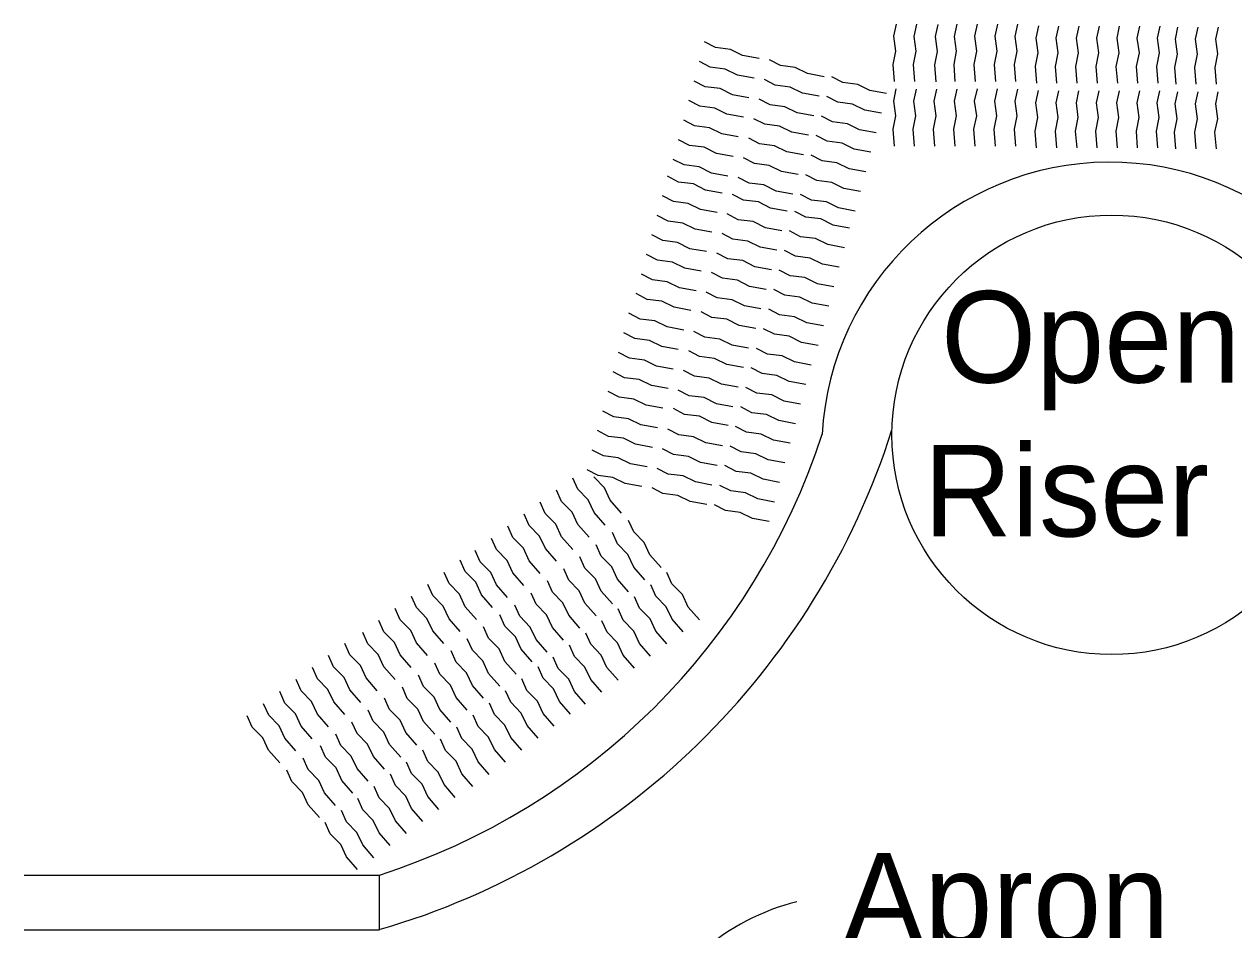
# Model space of a CAD drawing. Extents: x 539344 to 540004, y 1574686 to 1575110.
# Drawn here: x 539692.02 to 539725.07, y 1574776.96 to 1574801.69 of the extents above; entities that cross this region are included whole.
import ezdxf

# ---------------------------------------------------------------- set-up
doc = ezdxf.new("R2010")
doc.units = 0
doc.layers.add('Default', color=7, linetype='Continuous')

msp = doc.modelspace()

# ---------------------------------------------------------------- linework, layer by layer
at = {"layer": 'Default'}
for p, q in [((539692.024, 1574778.454), (539701.728, 1574778.454)), ((539701.728, 1574776.962), (539701.728, 1574778.454)), ((539692.024, 1574776.962), (539701.728, 1574776.962))]:
    msp.add_line(p, q, dxfattribs=at)
for points in [[(539715.804, 1574800.126), (539715.768, 1574800.586), (539715.84, 1574800.952), (539715.784, 1574801.36), (539715.858, 1574801.688)], [(539716.356, 1574800.126), (539716.32, 1574800.584), (539716.394, 1574800.952), (539716.338, 1574801.356), (539716.41, 1574801.688)], [(539716.938, 1574800.118), (539716.902, 1574800.576), (539716.978, 1574800.944), (539716.92, 1574801.348), (539716.994, 1574801.678)], [(539717.464, 1574800.126), (539717.428, 1574800.584), (539717.5, 1574800.952), (539717.444, 1574801.356), (539717.516, 1574801.688)], [(539718.018, 1574800.126), (539717.98, 1574800.586), (539718.054, 1574800.952), (539717.998, 1574801.36), (539718.07, 1574801.688)], [(539718.568, 1574800.128), (539718.53, 1574800.588), (539718.606, 1574800.956), (539718.55, 1574801.36), (539718.622, 1574801.688)], [(539719.12, 1574800.126), (539719.082, 1574800.584), (539719.158, 1574800.952), (539719.102, 1574801.356), (539719.174, 1574801.688)], [(539719.69, 1574800.078), (539719.654, 1574800.538), (539719.728, 1574800.906), (539719.67, 1574801.31), (539719.746, 1574801.64)], [(539720.24, 1574800.076), (539720.202, 1574800.536), (539720.278, 1574800.902), (539720.222, 1574801.31), (539720.294, 1574801.638)], [(539720.796, 1574800.076), (539720.756, 1574800.536), (539720.832, 1574800.902), (539720.776, 1574801.31), (539720.85, 1574801.638)], [(539721.35, 1574800.076), (539721.31, 1574800.536), (539721.386, 1574800.902), (539721.33, 1574801.31), (539721.402, 1574801.638)], [(539721.902, 1574800.076), (539721.862, 1574800.536), (539721.94, 1574800.902), (539721.882, 1574801.31), (539721.954, 1574801.638)], [(539722.452, 1574800.076), (539722.416, 1574800.534), (539722.492, 1574800.902), (539722.434, 1574801.308), (539722.508, 1574801.638)], [(539723.006, 1574800.076), (539722.968, 1574800.536), (539723.044, 1574800.902), (539722.988, 1574801.31), (539723.06, 1574801.638)], [(539723.496, 1574800.048), (539723.458, 1574800.508), (539723.532, 1574800.874), (539723.476, 1574801.28), (539723.548, 1574801.608)], [(539724.048, 1574800.048), (539724.012, 1574800.508), (539724.084, 1574800.874), (539724.03, 1574801.28), (539724.102, 1574801.608)], [(539724.602, 1574800.048), (539724.566, 1574800.508), (539724.638, 1574800.876), (539724.584, 1574801.28), (539724.656, 1574801.61)], [(539712.106, 1574800.748), (539711.652, 1574800.832), (539711.318, 1574800.998), (539710.912, 1574801.048), (539710.614, 1574801.204)], [(539711.964, 1574800.214), (539711.512, 1574800.298), (539711.178, 1574800.462), (539710.77, 1574800.514), (539710.472, 1574800.67)], [(539713.882, 1574800.254), (539713.428, 1574800.338), (539713.092, 1574800.504), (539712.686, 1574800.558), (539712.388, 1574800.712)], [(539713.74, 1574799.72), (539713.286, 1574799.804), (539712.95, 1574799.97), (539712.546, 1574800.022), (539712.248, 1574800.176)], [(539715.586, 1574799.792), (539715.132, 1574799.874), (539714.796, 1574800.042), (539714.392, 1574800.092), (539714.094, 1574800.248)], [(539711.822, 1574799.678), (539711.372, 1574799.76), (539711.036, 1574799.928), (539710.628, 1574799.978), (539710.328, 1574800.134)], [(539715.798, 1574798.36), (539715.762, 1574798.82), (539715.836, 1574799.186), (539715.78, 1574799.59), (539715.852, 1574799.922)], [(539716.348, 1574798.358), (539716.314, 1574798.818), (539716.386, 1574799.184), (539716.332, 1574799.588), (539716.404, 1574799.918)], [(539716.902, 1574798.358), (539716.866, 1574798.818), (539716.938, 1574799.184), (539716.886, 1574799.588), (539716.956, 1574799.918)], [(539717.456, 1574798.358), (539717.42, 1574798.818), (539717.494, 1574799.184), (539717.438, 1574799.588), (539717.512, 1574799.918)], [(539718.008, 1574798.36), (539717.974, 1574798.82), (539718.048, 1574799.186), (539717.992, 1574799.59), (539718.066, 1574799.922)], [(539718.562, 1574798.36), (539718.526, 1574798.822), (539718.598, 1574799.186), (539718.542, 1574799.59), (539718.616, 1574799.922)], [(539719.114, 1574798.358), (539719.078, 1574798.818), (539719.152, 1574799.184), (539719.096, 1574799.588), (539719.168, 1574799.918)], [(539719.684, 1574798.31), (539719.646, 1574798.77), (539719.72, 1574799.138), (539719.666, 1574799.544), (539719.738, 1574799.874)], [(539720.234, 1574798.31), (539720.198, 1574798.768), (539720.272, 1574799.138), (539720.216, 1574799.542), (539720.29, 1574799.872)], [(539720.79, 1574798.31), (539720.752, 1574798.768), (539720.824, 1574799.138), (539720.772, 1574799.542), (539720.842, 1574799.872)], [(539721.344, 1574798.31), (539721.306, 1574798.768), (539721.378, 1574799.138), (539721.324, 1574799.542), (539721.396, 1574799.872)], [(539721.896, 1574798.31), (539721.858, 1574798.768), (539721.932, 1574799.138), (539721.876, 1574799.542), (539721.95, 1574799.872)], [(539722.446, 1574798.31), (539722.41, 1574798.768), (539722.484, 1574799.136), (539722.428, 1574799.54), (539722.502, 1574799.872)], [(539723, 1574798.31), (539722.964, 1574798.768), (539723.038, 1574799.138), (539722.98, 1574799.542), (539723.056, 1574799.872)], [(539723.488, 1574798.282), (539723.452, 1574798.74), (539723.526, 1574799.106), (539723.47, 1574799.512), (539723.544, 1574799.842)], [(539724.042, 1574798.282), (539724.004, 1574798.74), (539724.08, 1574799.106), (539724.024, 1574799.512), (539724.098, 1574799.842)], [(539724.596, 1574798.282), (539724.558, 1574798.742), (539724.632, 1574799.106), (539724.578, 1574799.514), (539724.65, 1574799.842)], [(539711.678, 1574799.146), (539711.224, 1574799.23), (539710.89, 1574799.396), (539710.484, 1574799.448), (539710.186, 1574799.604)], [(539713.598, 1574799.186), (539713.144, 1574799.268), (539712.81, 1574799.434), (539712.404, 1574799.486), (539712.104, 1574799.64)], [(539715.444, 1574799.258), (539714.99, 1574799.34), (539714.658, 1574799.506), (539714.25, 1574799.558), (539713.952, 1574799.714)], [(539715.302, 1574798.722), (539714.85, 1574798.806), (539714.516, 1574798.97), (539714.11, 1574799.02), (539713.81, 1574799.178)], [(539711.534, 1574798.61), (539711.082, 1574798.696), (539710.75, 1574798.86), (539710.342, 1574798.914), (539710.042, 1574799.068)], [(539713.454, 1574798.654), (539713, 1574798.736), (539712.662, 1574798.902), (539712.258, 1574798.954), (539711.96, 1574799.108)], [(539711.394, 1574798.076), (539710.942, 1574798.16), (539710.606, 1574798.326), (539710.2, 1574798.378), (539709.9, 1574798.534)], [(539713.312, 1574798.118), (539712.858, 1574798.202), (539712.52, 1574798.368), (539712.116, 1574798.42), (539711.818, 1574798.574)], [(539715.158, 1574798.19), (539714.704, 1574798.272), (539714.37, 1574798.44), (539713.964, 1574798.49), (539713.666, 1574798.646)], [(539711.25, 1574797.54), (539710.8, 1574797.624), (539710.462, 1574797.79), (539710.056, 1574797.844), (539709.756, 1574797.998)], [(539713.168, 1574797.584), (539712.714, 1574797.668), (539712.38, 1574797.832), (539711.974, 1574797.884), (539711.676, 1574798.038)], [(539715.016, 1574797.654), (539714.56, 1574797.738), (539714.228, 1574797.904), (539713.822, 1574797.956), (539713.522, 1574798.11)], [(539711.094, 1574797.078), (539710.642, 1574797.16), (539710.308, 1574797.326), (539709.902, 1574797.378), (539709.602, 1574797.534)], [(539713.024, 1574797.05), (539712.572, 1574797.132), (539712.236, 1574797.298), (539711.832, 1574797.348), (539711.532, 1574797.504)], [(539714.874, 1574797.12), (539714.42, 1574797.2), (539714.086, 1574797.37), (539713.68, 1574797.422), (539713.38, 1574797.576)], [(539710.954, 1574796.544), (539710.5, 1574796.626), (539710.166, 1574796.792), (539709.76, 1574796.844), (539709.46, 1574797)], [(539712.87, 1574796.582), (539712.416, 1574796.666), (539712.082, 1574796.834), (539711.674, 1574796.884), (539711.376, 1574797.04)], [(539714.73, 1574796.584), (539714.276, 1574796.67), (539713.944, 1574796.836), (539713.536, 1574796.886), (539713.238, 1574797.042)], [(539712.728, 1574796.048), (539712.276, 1574796.132), (539711.94, 1574796.3), (539711.534, 1574796.35), (539711.234, 1574796.506)], [(539714.576, 1574796.12), (539714.124, 1574796.204), (539713.786, 1574796.37), (539713.38, 1574796.42), (539713.08, 1574796.578)], [(539710.808, 1574796.01), (539710.356, 1574796.092), (539710.022, 1574796.258), (539709.616, 1574796.31), (539709.316, 1574796.466)], [(539710.666, 1574795.478), (539710.212, 1574795.558), (539709.878, 1574795.726), (539709.472, 1574795.778), (539709.174, 1574795.934)], [(539712.586, 1574795.518), (539712.13, 1574795.598), (539711.796, 1574795.766), (539711.388, 1574795.816), (539711.09, 1574795.972)], [(539714.432, 1574795.586), (539713.98, 1574795.67), (539713.644, 1574795.836), (539713.238, 1574795.886), (539712.938, 1574796.044)], [(539714.29, 1574795.054), (539713.838, 1574795.136), (539713.5, 1574795.302), (539713.094, 1574795.354), (539712.796, 1574795.51)], [(539710.522, 1574794.942), (539710.07, 1574795.024), (539709.736, 1574795.19), (539709.33, 1574795.242), (539709.03, 1574795.4)], [(539712.442, 1574794.984), (539711.988, 1574795.064), (539711.654, 1574795.234), (539711.246, 1574795.282), (539710.948, 1574795.438)], [(539710.38, 1574794.406), (539709.926, 1574794.488), (539709.592, 1574794.656), (539709.186, 1574794.706), (539708.886, 1574794.862)], [(539712.298, 1574794.448), (539711.844, 1574794.53), (539711.51, 1574794.698), (539711.102, 1574794.75), (539710.804, 1574794.906)], [(539714.146, 1574794.52), (539713.694, 1574794.602), (539713.356, 1574794.768), (539712.952, 1574794.82), (539712.65, 1574794.976)], [(539710.236, 1574793.874), (539709.78, 1574793.958), (539709.448, 1574794.124), (539709.042, 1574794.174), (539708.742, 1574794.332)], [(539712.154, 1574793.912), (539711.7, 1574793.994), (539711.368, 1574794.162), (539710.96, 1574794.212), (539710.66, 1574794.368)], [(539714.004, 1574793.986), (539713.55, 1574794.068), (539713.214, 1574794.234), (539712.808, 1574794.288), (539712.508, 1574794.44)], [(539713.86, 1574793.45), (539713.408, 1574793.532), (539713.07, 1574793.698), (539712.664, 1574793.75), (539712.366, 1574793.908)], [(539710.044, 1574793.334), (539709.59, 1574793.42), (539709.254, 1574793.586), (539708.85, 1574793.636), (539708.548, 1574793.794)], [(539712.01, 1574793.38), (539711.558, 1574793.464), (539711.222, 1574793.632), (539710.816, 1574793.68), (539710.516, 1574793.838)], [(539709.896, 1574792.804), (539709.446, 1574792.886), (539709.11, 1574793.054), (539708.704, 1574793.104), (539708.404, 1574793.26)], [(539711.816, 1574792.842), (539711.366, 1574792.924), (539711.03, 1574793.092), (539710.624, 1574793.144), (539710.324, 1574793.3)], [(539713.716, 1574792.918), (539713.264, 1574793), (539712.926, 1574793.166), (539712.522, 1574793.22), (539712.222, 1574793.374)], [(539709.758, 1574792.27), (539709.304, 1574792.354), (539708.968, 1574792.518), (539708.56, 1574792.572), (539708.262, 1574792.726)], [(539711.674, 1574792.31), (539711.218, 1574792.392), (539710.884, 1574792.562), (539710.476, 1574792.61), (539710.18, 1574792.766)], [(539713.524, 1574792.38), (539713.07, 1574792.464), (539712.734, 1574792.63), (539712.33, 1574792.68), (539712.03, 1574792.836)], [(539711.532, 1574791.778), (539711.078, 1574791.862), (539710.742, 1574792.026), (539710.336, 1574792.078), (539710.036, 1574792.232)], [(539713.378, 1574791.846), (539712.924, 1574791.93), (539712.59, 1574792.096), (539712.184, 1574792.146), (539711.884, 1574792.304)], [(539709.614, 1574791.736), (539709.16, 1574791.818), (539708.824, 1574791.984), (539708.422, 1574792.036), (539708.118, 1574792.192)], [(539709.472, 1574791.2), (539709.018, 1574791.282), (539708.682, 1574791.45), (539708.278, 1574791.502), (539707.976, 1574791.658)], [(539711.388, 1574791.244), (539710.938, 1574791.326), (539710.6, 1574791.492), (539710.194, 1574791.542), (539709.894, 1574791.698)], [(539713.236, 1574791.312), (539712.784, 1574791.398), (539712.448, 1574791.564), (539712.044, 1574791.614), (539711.742, 1574791.77)], [(539713.096, 1574790.778), (539712.64, 1574790.862), (539712.306, 1574791.028), (539711.902, 1574791.08), (539711.602, 1574791.236)], [(539709.328, 1574790.666), (539708.876, 1574790.75), (539708.538, 1574790.916), (539708.134, 1574790.968), (539707.832, 1574791.122)], [(539711.262, 1574790.734), (539710.81, 1574790.816), (539710.474, 1574790.984), (539710.068, 1574791.034), (539709.766, 1574791.19)], [(539709.186, 1574790.132), (539708.73, 1574790.216), (539708.396, 1574790.382), (539707.988, 1574790.434), (539707.688, 1574790.59)], [(539711.102, 1574790.174), (539710.65, 1574790.256), (539710.314, 1574790.422), (539709.91, 1574790.474), (539709.608, 1574790.628)], [(539712.952, 1574790.244), (539712.496, 1574790.326), (539712.162, 1574790.492), (539711.758, 1574790.546), (539711.458, 1574790.7)], [(539709.042, 1574789.598), (539708.588, 1574789.68), (539708.252, 1574789.846), (539707.848, 1574789.898), (539707.546, 1574790.054)], [(539710.958, 1574789.64), (539710.504, 1574789.724), (539710.17, 1574789.888), (539709.762, 1574789.94), (539709.464, 1574790.096)], [(539712.808, 1574789.708), (539712.354, 1574789.794), (539712.018, 1574789.958), (539711.614, 1574790.012), (539711.316, 1574790.166)], [(539710.814, 1574789.104), (539710.364, 1574789.188), (539710.028, 1574789.354), (539709.622, 1574789.404), (539709.32, 1574789.56)], [(539712.664, 1574789.176), (539712.21, 1574789.26), (539711.876, 1574789.426), (539711.472, 1574789.478), (539711.168, 1574789.634)], [(539707.898, 1574788.008), (539707.594, 1574788.356), (539707.436, 1574788.696), (539707.15, 1574788.988), (539707.014, 1574789.296)], [(539708.898, 1574789.062), (539708.444, 1574789.146), (539708.11, 1574789.314), (539707.702, 1574789.366), (539707.402, 1574789.52)], [(539708.34, 1574788.34), (539708.038, 1574788.688), (539707.88, 1574789.026), (539707.594, 1574789.318), (539707.59, 1574789.328)], [(539707.456, 1574787.678), (539707.154, 1574788.026), (539706.994, 1574788.362), (539706.706, 1574788.656), (539706.57, 1574788.964)], [(539710.672, 1574788.57), (539710.218, 1574788.654), (539709.882, 1574788.82), (539709.476, 1574788.872), (539709.178, 1574789.028)], [(539712.522, 1574788.638), (539712.066, 1574788.724), (539711.732, 1574788.89), (539711.328, 1574788.942), (539711.028, 1574789.096)], [(539707.01, 1574787.348), (539706.708, 1574787.692), (539706.548, 1574788.032), (539706.262, 1574788.326), (539706.124, 1574788.634)], [(539706.566, 1574787.022), (539706.264, 1574787.37), (539706.104, 1574787.706), (539705.818, 1574788), (539705.682, 1574788.308)], [(539712.376, 1574788.108), (539711.924, 1574788.192), (539711.588, 1574788.358), (539711.184, 1574788.41), (539710.882, 1574788.564)], [(539706.122, 1574786.69), (539705.82, 1574787.038), (539705.662, 1574787.376), (539705.376, 1574787.672), (539705.238, 1574787.978)], [(539709.424, 1574786.848), (539709.122, 1574787.196), (539708.962, 1574787.536), (539708.676, 1574787.83), (539708.538, 1574788.136)], [(539705.676, 1574786.36), (539705.376, 1574786.706), (539705.216, 1574787.046), (539704.932, 1574787.34), (539704.792, 1574787.648)], [(539708.98, 1574786.516), (539708.678, 1574786.866), (539708.52, 1574787.204), (539708.234, 1574787.498), (539708.096, 1574787.806)], [(539705.232, 1574786.03), (539704.932, 1574786.376), (539704.77, 1574786.716), (539704.486, 1574787.01), (539704.348, 1574787.318)], [(539708.538, 1574786.186), (539708.234, 1574786.534), (539708.076, 1574786.874), (539707.79, 1574787.166), (539707.652, 1574787.474)], [(539704.822, 1574785.764), (539704.52, 1574786.11), (539704.36, 1574786.45), (539704.074, 1574786.742), (539703.938, 1574787.052)], [(539708.094, 1574785.858), (539707.79, 1574786.204), (539707.63, 1574786.542), (539707.346, 1574786.836), (539707.208, 1574787.142)], [(539704.38, 1574785.434), (539704.076, 1574785.78), (539703.918, 1574786.12), (539703.632, 1574786.412), (539703.494, 1574786.72)], [(539707.65, 1574785.53), (539707.346, 1574785.878), (539707.186, 1574786.218), (539706.9, 1574786.508), (539706.764, 1574786.816)], [(539710.47, 1574785.426), (539710.168, 1574785.772), (539710.008, 1574786.112), (539709.722, 1574786.404), (539709.586, 1574786.712)], [(539703.934, 1574785.106), (539703.632, 1574785.452), (539703.472, 1574785.792), (539703.186, 1574786.084), (539703.05, 1574786.392)], [(539707.206, 1574785.2), (539706.902, 1574785.548), (539706.742, 1574785.886), (539706.458, 1574786.18), (539706.32, 1574786.486)], [(539710.028, 1574785.094), (539709.724, 1574785.442), (539709.564, 1574785.782), (539709.28, 1574786.072), (539709.142, 1574786.382)], [(539703.492, 1574784.778), (539703.188, 1574785.124), (539703.028, 1574785.462), (539702.744, 1574785.756), (539702.606, 1574786.064)], [(539706.76, 1574784.87), (539706.458, 1574785.218), (539706.298, 1574785.556), (539706.012, 1574785.848), (539705.874, 1574786.156)], [(539709.584, 1574784.764), (539709.28, 1574785.112), (539709.124, 1574785.448), (539708.836, 1574785.742), (539708.7, 1574786.05)], [(539703.046, 1574784.448), (539702.744, 1574784.794), (539702.584, 1574785.134), (539702.298, 1574785.426), (539702.162, 1574785.736)], [(539706.316, 1574784.542), (539706.012, 1574784.888), (539705.852, 1574785.226), (539705.568, 1574785.52), (539705.43, 1574785.826)], [(539709.14, 1574784.434), (539708.838, 1574784.78), (539708.678, 1574785.118), (539708.392, 1574785.41), (539708.254, 1574785.72)], [(539702.6, 1574784.118), (539702.298, 1574784.464), (539702.138, 1574784.804), (539701.852, 1574785.096), (539701.716, 1574785.404)], [(539705.906, 1574784.272), (539705.602, 1574784.62), (539705.444, 1574784.96), (539705.156, 1574785.252), (539705.02, 1574785.56)], [(539708.696, 1574784.108), (539708.39, 1574784.454), (539708.234, 1574784.792), (539707.948, 1574785.086), (539707.81, 1574785.392)], [(539702.156, 1574783.79), (539701.852, 1574784.14), (539701.696, 1574784.478), (539701.41, 1574784.77), (539701.272, 1574785.078)], [(539705.462, 1574783.942), (539705.158, 1574784.288), (539705, 1574784.63), (539704.714, 1574784.922), (539704.576, 1574785.23)], [(539708.25, 1574783.776), (539707.946, 1574784.124), (539707.79, 1574784.46), (539707.504, 1574784.756), (539707.366, 1574785.062)], [(539701.672, 1574783.488), (539701.368, 1574783.836), (539701.208, 1574784.176), (539700.924, 1574784.468), (539700.786, 1574784.778)], [(539705.018, 1574783.616), (539704.712, 1574783.962), (539704.556, 1574784.302), (539704.268, 1574784.594), (539704.13, 1574784.902)], [(539707.806, 1574783.446), (539707.502, 1574783.792), (539707.346, 1574784.13), (539707.06, 1574784.424), (539706.922, 1574784.734)], [(539701.226, 1574783.166), (539700.924, 1574783.51), (539700.764, 1574783.848), (539700.478, 1574784.142), (539700.34, 1574784.45)], [(539704.574, 1574783.286), (539704.27, 1574783.632), (539704.112, 1574783.972), (539703.824, 1574784.266), (539703.688, 1574784.574)], [(539707.362, 1574783.116), (539707.06, 1574783.464), (539706.902, 1574783.802), (539706.616, 1574784.094), (539706.478, 1574784.404)], [(539700.784, 1574782.834), (539700.48, 1574783.18), (539700.32, 1574783.518), (539700.036, 1574783.814), (539699.898, 1574784.12)], [(539704.13, 1574782.956), (539703.824, 1574783.304), (539703.668, 1574783.642), (539703.38, 1574783.936), (539703.242, 1574784.244)], [(539706.952, 1574782.85), (539706.65, 1574783.196), (539706.49, 1574783.536), (539706.202, 1574783.828), (539706.066, 1574784.138)], [(539700.34, 1574782.502), (539700.036, 1574782.85), (539699.876, 1574783.19), (539699.592, 1574783.482), (539699.452, 1574783.792)], [(539703.684, 1574782.626), (539703.378, 1574782.974), (539703.222, 1574783.312), (539702.934, 1574783.606), (539702.796, 1574783.914)], [(539706.508, 1574782.52), (539706.206, 1574782.866), (539706.046, 1574783.206), (539705.76, 1574783.498), (539705.622, 1574783.808)], [(539699.896, 1574782.174), (539699.59, 1574782.52), (539699.432, 1574782.86), (539699.148, 1574783.152), (539699.008, 1574783.462)], [(539702.752, 1574782), (539702.45, 1574782.344), (539702.292, 1574782.686), (539702.006, 1574782.978), (539701.868, 1574783.286)], [(539703.24, 1574782.3), (539702.938, 1574782.648), (539702.778, 1574782.988), (539702.492, 1574783.278), (539702.356, 1574783.588)], [(539706.064, 1574782.192), (539705.762, 1574782.538), (539705.6, 1574782.878), (539705.316, 1574783.172), (539705.178, 1574783.48)], [(539699.45, 1574781.844), (539699.148, 1574782.192), (539698.986, 1574782.53), (539698.704, 1574782.824), (539698.564, 1574783.132)], [(539702.31, 1574781.672), (539702.004, 1574782.02), (539701.846, 1574782.36), (539701.56, 1574782.652), (539701.424, 1574782.96)], [(539705.62, 1574781.864), (539705.318, 1574782.21), (539705.156, 1574782.55), (539704.872, 1574782.842), (539704.734, 1574783.15)], [(539699.006, 1574781.516), (539698.702, 1574781.864), (539698.544, 1574782.202), (539698.256, 1574782.496), (539698.118, 1574782.804)], [(539701.866, 1574781.344), (539701.564, 1574781.692), (539701.404, 1574782.028), (539701.118, 1574782.322), (539700.98, 1574782.63)], [(539705.176, 1574781.534), (539704.872, 1574781.88), (539704.712, 1574782.22), (539704.428, 1574782.514), (539704.288, 1574782.82)], [(539701.422, 1574781.014), (539701.12, 1574781.36), (539700.96, 1574781.698), (539700.674, 1574781.99), (539700.534, 1574782.3)], [(539704.73, 1574781.204), (539704.428, 1574781.55), (539704.266, 1574781.89), (539703.982, 1574782.184), (539703.844, 1574782.492)], [(539701.006, 1574780.694), (539700.704, 1574781.04), (539700.544, 1574781.382), (539700.258, 1574781.672), (539700.12, 1574781.982)], [(539704.286, 1574780.876), (539703.984, 1574781.222), (539703.822, 1574781.562), (539703.538, 1574781.856), (539703.4, 1574782.164)], [(539700.532, 1574780.356), (539700.232, 1574780.702), (539700.07, 1574781.04), (539699.784, 1574781.332), (539699.646, 1574781.642)], [(539703.802, 1574780.574), (539703.498, 1574780.924), (539703.338, 1574781.262), (539703.054, 1574781.552), (539702.916, 1574781.862)], [(539700.088, 1574780.026), (539699.786, 1574780.374), (539699.626, 1574780.712), (539699.338, 1574781.006), (539699.202, 1574781.314)], [(539703.356, 1574780.248), (539703.052, 1574780.598), (539702.894, 1574780.934), (539702.608, 1574781.226), (539702.47, 1574781.536)], [(539702.912, 1574779.918), (539702.61, 1574780.268), (539702.452, 1574780.606), (539702.166, 1574780.898), (539702.028, 1574781.208)], [(539702.468, 1574779.588), (539702.166, 1574779.938), (539702.006, 1574780.274), (539701.722, 1574780.566), (539701.584, 1574780.876)], [(539702.024, 1574779.258), (539701.72, 1574779.606), (539701.56, 1574779.944), (539701.278, 1574780.238), (539701.138, 1574780.546)], [(539701.578, 1574778.928), (539701.276, 1574779.278), (539701.116, 1574779.616), (539700.834, 1574779.908), (539700.694, 1574780.216)], [(539701.134, 1574778.602), (539700.832, 1574778.95), (539700.674, 1574779.288), (539700.388, 1574779.58), (539700.25, 1574779.89)]]:
    msp.add_lwpolyline(points, dxfattribs=at)
msp.add_circle((539721.734, 1574790.475), 6.001, dxfattribs=at)
for centre, radius, start, end in [((539721.684, 1574790.049), 7.872, 3.8637, 176.7999), ((539695.922, 1574796.934), 20.797, 286.2077, 342.2932), ((539696.012, 1574796.297), 18.735, 287.761, 341.9398), ((539714.649, 1574771.63), 6.278, 103.9516, 157.5089)]:
    msp.add_arc(centre, radius, start, end, dxfattribs=at)

# ---------------------------------------------------------------- texts
for s, p in [('Open', (539717.073, 1574791.901)), ('Riser', (539716.595, 1574787.701)), ('Apron', (539714.387, 1574776.559))]:
    msp.add_text(s, height=2.5, dxfattribs=at).set_placement(p)

doc.saveas('drawing.dxf')
